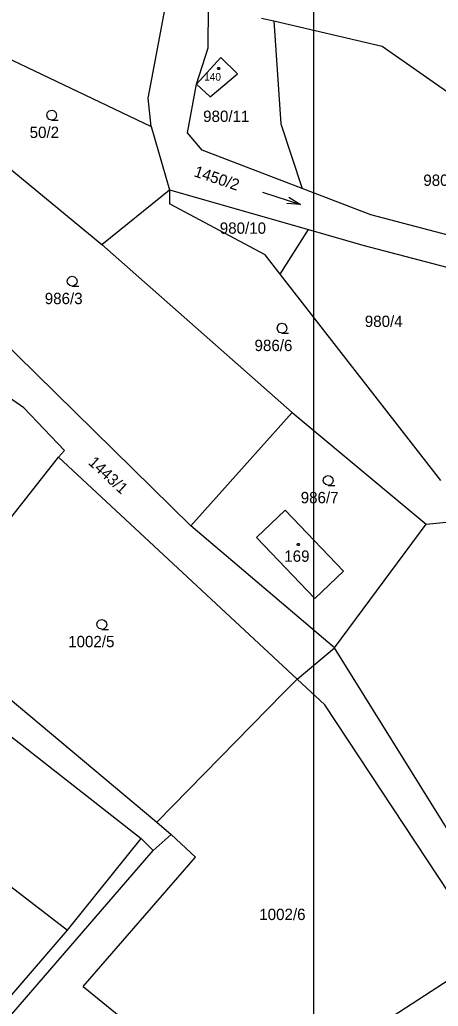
# Model space of a CAD drawing. Extents: x -852001 to -842497, y -1063614 to -1052182.
# Drawn here: x -849187.1 to -849124.2, y -1056403.5 to -1056255.4 of the extents above; entities that cross this region are included whole.
import ezdxf

# ---------------------------------------------------------------- set-up
doc = ezdxf.new("R2010")
doc.units = 0
for name, color, linetype in [('Default', 7, 'Continuous'), ('KN_HRANICE', 7, 'Continuous'), ('KN_KULTURY', 7, 'Continuous'), ('KN_PARCELY', 7, 'Continuous'), ('LEGENDA', 7, 'Continuous')]:
    doc.layers.add(name, color=color, linetype=linetype)

# ---------------------------------------------------------------- blocks, each defined once
blk = doc.blocks.new('304')
at = {"layer": 'Default'}
blk.add_lwpolyline([(0, 0), (-0.38, 0.1), (-0.65, 0.37), (-0.75, 0.74), (-0.65, 1.11), (-0.38, 1.38), (-0.01, 1.48), (0.36, 1.38), (0.63, 1.11), (0.73, 0.73), (0.63, 0.35), (0.36, 0.08), (-0.02, -0.02), (0.98, -0.02)], dxfattribs=at)
blk = doc.blocks.new('802')
at = {"layer": 'Default'}
blk.add_line((-3, 0), (3, 0), dxfattribs=at)
blk.add_lwpolyline([(1, 0.5), (3, 0), (1, -0.5)], dxfattribs=at)
blk = doc.blocks.new('402')
at = {"layer": 'Default'}
blk.add_lwpolyline([(0.09, 0.15), (0.18, 0), (0.09, -0.15), (-0.09, -0.15), (-0.18, 0), (-0.09, 0.15), (0.09, 0.15)], dxfattribs=at)

msp = doc.modelspace()

# ---------------------------------------------------------------- linework, layer by layer
at = {"layer": 'KN_HRANICE'}
for p, q in [((-849166.92, -1056262.43), (-849164.8, -1056251.16)), ((-849166.92, -1056262.43), (-849164.8, -1056251.16)), ((-849158.79, -1056259.59), (-849158.72, -1056253.46)), ((-849158.79, -1056259.59), (-849158.72, -1056253.46)), ((-849150.75, -1056255.14), (-849148.92, -1056255.56)), ((-849150.75, -1056255.14), (-849148.92, -1056255.56)), ((-849148.92, -1056255.56), (-849132.64, -1056259.34)), ((-849148.92, -1056255.56), (-849147.84, -1056271.04)), ((-849148.92, -1056255.56), (-849132.64, -1056259.34)), ((-849148.92, -1056255.56), (-849147.84, -1056271.04)), ((-849195.81, -1056257.87), (-849167.34, -1056271.45)), ((-849195.81, -1056257.87), (-849167.34, -1056271.45)), ((-849160.55, -1056265.07), (-849158.79, -1056259.59)), ((-849160.55, -1056265.07), (-849158.79, -1056259.59)), ((-849132.64, -1056259.34), (-849099.56, -1056282.53)), ((-849132.64, -1056259.34), (-849099.56, -1056282.53)), ((-849156.88, -1056261.06), (-849160.55, -1056265.07)), ((-849156.88, -1056261.06), (-849160.55, -1056265.07)), ((-849154.35, -1056263.5), (-849156.88, -1056261.06)), ((-849154.35, -1056263.5), (-849156.88, -1056261.06)), ((-849167.78, -1056267.19), (-849166.92, -1056262.43)), ((-849167.78, -1056267.19), (-849166.92, -1056262.43)), ((-849158.48, -1056266.96), (-849154.35, -1056263.5)), ((-849158.48, -1056266.96), (-849154.35, -1056263.5)), ((-849161.91, -1056272.4), (-849160.55, -1056265.07)), ((-849161.91, -1056272.4), (-849160.55, -1056265.07)), ((-849160.55, -1056265.07), (-849158.48, -1056266.96)), ((-849160.55, -1056265.07), (-849158.48, -1056266.96)), ((-849167.34, -1056271.45), (-849167.78, -1056267.19)), ((-849167.34, -1056271.45), (-849167.78, -1056267.19)), ((-849167.34, -1056271.45), (-849164.6, -1056280.95)), ((-849167.34, -1056271.45), (-849164.6, -1056280.95)), ((-849147.84, -1056271.04), (-849144.65, -1056280.72)), ((-849147.84, -1056271.04), (-849144.65, -1056280.72)), ((-849159.69, -1056274.96), (-849161.91, -1056272.4)), ((-849159.69, -1056274.96), (-849161.91, -1056272.4)), ((-849144.65, -1056280.72), (-849159.69, -1056274.96)), ((-849144.65, -1056280.72), (-849159.69, -1056274.96)), ((-849189.99, -1056276.6), (-849174.78, -1056289.12)), ((-849189.99, -1056276.6), (-849174.78, -1056289.12)), ((-849174.78, -1056289.12), (-849164.6, -1056280.95)), ((-849174.78, -1056289.12), (-849164.6, -1056280.95)), ((-849164.6, -1056280.95), (-849143.72, -1056286.9)), ((-849164.6, -1056280.95), (-849164.59, -1056283.02)), ((-849164.6, -1056280.95), (-849143.72, -1056286.9)), ((-849164.6, -1056280.95), (-849164.59, -1056283.02)), ((-849134.31, -1056284.69), (-849144.65, -1056280.72)), ((-849134.31, -1056284.69), (-849144.65, -1056280.72)), ((-849150.22, -1056290.7), (-849164.59, -1056283.02)), ((-849150.22, -1056290.7), (-849164.59, -1056283.02)), ((-849119.35, -1056288.63), (-849134.31, -1056284.69)), ((-849119.35, -1056288.63), (-849134.31, -1056284.69)), ((-849147.96, -1056293.59), (-849143.72, -1056286.9)), ((-849147.96, -1056293.59), (-849143.72, -1056286.9)), ((-849143.72, -1056286.9), (-849135.51, -1056289.24)), ((-849143.72, -1056286.9), (-849135.51, -1056289.24)), ((-849174.78, -1056289.12), (-849146.16, -1056314.38)), ((-849174.78, -1056289.12), (-849146.16, -1056314.38)), ((-849135.51, -1056289.24), (-849120.55, -1056293.17)), ((-849135.51, -1056289.24), (-849120.55, -1056293.17)), ((-849147.96, -1056293.59), (-849150.22, -1056290.7)), ((-849147.96, -1056293.59), (-849150.22, -1056290.7)), ((-849161.41, -1056331.37), (-849201.97, -1056291.61)), ((-849161.41, -1056331.37), (-849201.97, -1056291.61)), ((-849123.81, -1056324.58), (-849147.96, -1056293.59)), ((-849123.81, -1056324.58), (-849147.96, -1056293.59)), ((-849186.5, -1056313.66), (-849190.95, -1056310.59)), ((-849186.5, -1056313.66), (-849190.95, -1056310.59)), ((-849180.36, -1056320.1), (-849186.5, -1056313.66)), ((-849180.36, -1056320.1), (-849186.5, -1056313.66)), ((-849161.41, -1056331.37), (-849146.16, -1056314.38)), ((-849161.41, -1056331.37), (-849146.16, -1056314.38)), ((-849146.16, -1056314.38), (-849125.99, -1056331.15)), ((-849146.16, -1056314.38), (-849125.99, -1056331.15)), ((-849181.26, -1056321.09), (-849180.36, -1056320.1)), ((-849181.26, -1056321.09), (-849180.36, -1056320.1)), ((-849201.5, -1056346.7), (-849181.26, -1056321.09)), ((-849201.5, -1056346.7), (-849181.26, -1056321.09)), ((-849181.26, -1056321.09), (-849145.42, -1056354.4)), ((-849181.26, -1056321.09), (-849145.42, -1056354.4)), ((-849151.51, -1056333.16), (-849147.19, -1056329.03)), ((-849151.51, -1056333.16), (-849147.19, -1056329.03)), ((-849147.19, -1056329.03), (-849138.43, -1056338.18)), ((-849147.19, -1056329.03), (-849138.43, -1056338.18)), ((-849125.99, -1056331.15), (-849122.51, -1056330.8)), ((-849125.99, -1056331.15), (-849122.51, -1056330.8)), ((-849139.79, -1056349.71), (-849161.41, -1056331.37)), ((-849139.79, -1056349.71), (-849161.41, -1056331.37)), ((-849139.79, -1056349.71), (-849125.99, -1056331.15)), ((-849139.79, -1056349.71), (-849125.99, -1056331.15)), ((-849142.75, -1056342.31), (-849151.51, -1056333.16)), ((-849142.75, -1056342.31), (-849151.51, -1056333.16)), ((-849223.07, -1056335.94), (-849168.88, -1056378.32)), ((-849223.07, -1056335.94), (-849168.88, -1056378.32)), ((-849138.43, -1056338.18), (-849142.75, -1056342.31)), ((-849138.43, -1056338.18), (-849142.75, -1056342.31)), ((-849201.5, -1056346.7), (-849166.49, -1056375.89)), ((-849201.5, -1056346.7), (-849166.49, -1056375.89)), ((-849145.42, -1056354.4), (-849139.79, -1056349.71)), ((-849145.42, -1056354.4), (-849139.79, -1056349.71)), ((-849112.51, -1056393.58), (-849139.79, -1056349.71)), ((-849112.51, -1056393.58), (-849139.79, -1056349.71)), ((-849145.42, -1056354.4), (-849147.47, -1056356.49)), ((-849145.42, -1056354.4), (-849147.47, -1056356.49)), ((-849145.42, -1056354.4), (-849141.27, -1056358.26)), ((-849145.42, -1056354.4), (-849141.27, -1056358.26)), ((-849147.47, -1056356.49), (-849166.49, -1056375.89)), ((-849147.47, -1056356.49), (-849166.49, -1056375.89)), ((-849116.66, -1056395.53), (-849141.27, -1056358.26)), ((-849116.66, -1056395.53), (-849141.27, -1056358.26)), ((-849215.1, -1056365.17), (-849179.95, -1056392.09)), ((-849215.1, -1056365.17), (-849179.95, -1056392.09)), ((-849166.49, -1056375.89), (-849164.34, -1056377.76)), ((-849166.49, -1056375.89), (-849164.34, -1056377.76)), ((-849167.05, -1056380.13), (-849164.34, -1056377.76)), ((-849167.05, -1056380.13), (-849164.34, -1056377.76)), ((-849160.67, -1056381.14), (-849164.34, -1056377.76)), ((-849160.67, -1056381.14), (-849164.34, -1056377.76)), ((-849179.95, -1056392.09), (-849168.88, -1056378.32)), ((-849179.95, -1056392.09), (-849168.88, -1056378.32)), ((-849168.88, -1056378.32), (-849167.05, -1056380.13)), ((-849168.88, -1056378.32), (-849167.05, -1056380.13)), ((-849207.62, -1056426.96), (-849167.05, -1056380.13)), ((-849207.62, -1056426.96), (-849167.05, -1056380.13)), ((-849177.57, -1056400.57), (-849160.67, -1056381.14)), ((-849177.57, -1056400.57), (-849160.67, -1056381.14)), ((-849210.21, -1056427.21), (-849179.95, -1056392.09)), ((-849210.21, -1056427.21), (-849179.95, -1056392.09)), ((-849153.92, -1056419.76), (-849122.42, -1056399.43)), ((-849153.92, -1056419.76), (-849122.42, -1056399.43)), ((-849177.57, -1056400.57), (-849153.92, -1056419.76)), ((-849177.57, -1056400.57), (-849153.92, -1056419.76))]:
    msp.add_line(p, q, dxfattribs=at)
at = {"layer": 'LEGENDA'}
msp.add_lwpolyline([(-849142.95, -1056625.24), (-848548.95, -1056625.24), (-848548.95, -1056205.24), (-849142.95, -1056205.24)], close=True, dxfattribs=at)

# ---------------------------------------------------------------- block references
at = {"layer": 'KN_KULTURY'}
for name, p in [('402', (-849157.21, -1056262.73)), ('402', (-849157.21, -1056262.73)), ('304', (-849182.3, -1056270.45)), ('304', (-849182.3, -1056270.45)), ('304', (-849179.22, -1056295.4)), ('304', (-849179.22, -1056295.4)), ('304', (-849147.68, -1056302.45)), ('304', (-849147.68, -1056302.45)), ('304', (-849140.74, -1056325.3)), ('304', (-849140.74, -1056325.3)), ('402', (-849145.24, -1056334.2)), ('402', (-849145.24, -1056334.2)), ('304', (-849174.77, -1056346.92)), ('304', (-849174.77, -1056346.92))]:
    msp.add_blockref(name, p, dxfattribs=at)
at = {"layer": 'KN_KULTURY', "rotation": -17.944195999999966}
msp.add_blockref('802', (-849147.75, -1056282.2), dxfattribs=at)
msp.add_blockref('802', (-849147.75, -1056282.2), dxfattribs=at)

# ---------------------------------------------------------------- texts
at = {"layer": 'KN_PARCELY'}
for s, height, p in [('140', 1.14, (-849159.4, -1056264.54)), ('140', 1.14, (-849159.4, -1056264.54)), ('980/11', 1.7, (-849159.54, -1056270.74)), ('980/11', 1.7, (-849159.54, -1056270.74)), ('50/2', 1.7, (-849185.62, -1056273.15)), ('50/2', 1.7, (-849185.62, -1056273.15)), ('980/3', 1.7, (-849126.44, -1056280.34)), ('980/3', 1.7, (-849126.44, -1056280.34)), ('980/10', 1.7, (-849157.04, -1056287.53)), ('980/10', 1.7, (-849157.04, -1056287.53)), ('986/3', 1.7, (-849183.35, -1056298.1)), ('986/3', 1.7, (-849183.35, -1056298.1)), ('980/4', 1.7, (-849135.24, -1056301.53)), ('980/4', 1.7, (-849135.24, -1056301.53)), ('986/6', 1.7, (-849151.81, -1056305.15)), ('986/6', 1.7, (-849151.81, -1056305.15)), ('986/7', 1.7, (-849144.87, -1056328)), ('986/7', 1.7, (-849144.87, -1056328)), ('169', 1.7, (-849147.34, -1056336.79)), ('169', 1.7, (-849147.34, -1056336.79)), ('1002/5', 1.7, (-849179.83, -1056349.62)), ('1002/5', 1.7, (-849179.83, -1056349.62)), ('1002/6', 1.7, (-849151.1, -1056390.59)), ('1002/6', 1.7, (-849151.1, -1056390.59))]:
    msp.add_text(s, height=height, dxfattribs=at).set_placement(p)
for s, rotation, p in [('1450/2', 341.54, (-849161.04, -1056278.88)), ('1450/2', 341.54, (-849161.04, -1056278.88)), ('1443/1', 317.189, (-849176.92, -1056322.03)), ('1443/1', 317.189, (-849176.92, -1056322.03))]:
    msp.add_text(s, height=1.7, rotation=rotation, dxfattribs=at).set_placement(p)

doc.saveas('drawing.dxf')
